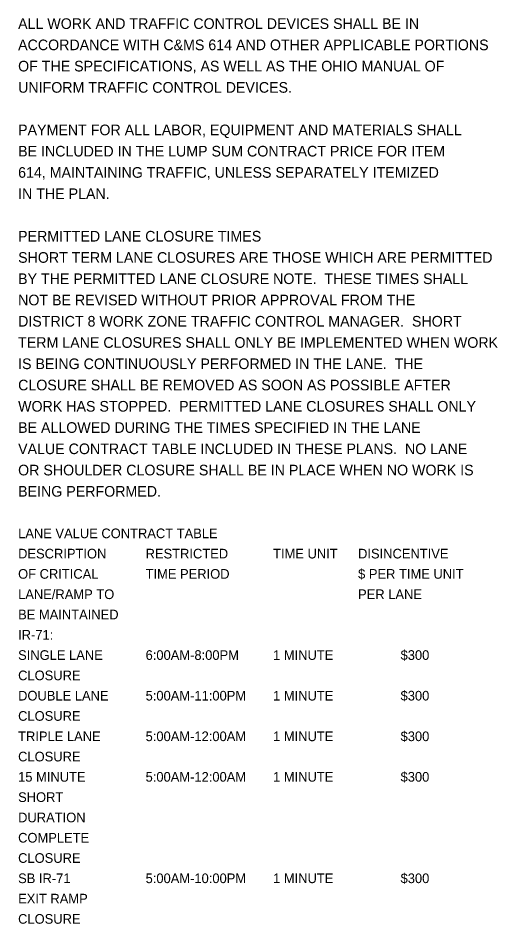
# Model space of a CAD drawing. Extents: x -98 to 46, y -2 to 66.
# Drawn here: x -97.61 to -91.28, y 54.03 to 65.96 of the extents above; entities that cross this region are included whole.
import ezdxf

# ---------------------------------------------------------------- set-up
doc = ezdxf.new("R2010")
doc.units = 0
doc.layers.add('Default', color=7, linetype='Continuous')

msp = doc.modelspace()

# ---------------------------------------------------------------- texts
at = {"layer": 'Default'}
for s, height, p in [('ALL WORK AND TRAFFIC CONTROL DEVICES SHALL BE IN ', 0.14, (-97.607, 65.818)), ('ACCORDANCE WITH C&MS 614 AND OTHER APPLICABLE PORTIONS ', 0.14, (-97.607, 65.538)), ('OF THE SPECIFICATIONS, AS WELL AS THE OHIO MANUAL OF ', 0.14, (-97.607, 65.258)), ('UNIFORM TRAFFIC CONTROL DEVICES.', 0.14, (-97.607, 64.978)), ('PAYMENT FOR ALL LABOR, EQUIPMENT AND MATERIALS SHALL ', 0.14, (-97.607, 64.418)), ('BE INCLUDED IN THE LUMP SUM CONTRACT PRICE FOR ITEM ', 0.14, (-97.607, 64.138)), ('614, MAINTAINING TRAFFIC, UNLESS SEPARATELY ITEMIZED ', 0.14, (-97.607, 63.858)), ('IN THE PLAN.', 0.14, (-97.607, 63.578)), ('PERMITTED LANE CLOSURE TIMES', 0.14, (-97.607, 63.018)), ('SHORT TERM LANE CLOSURES ARE THOSE WHICH ARE PERMITTED ', 0.14, (-97.607, 62.738)), ('BY THE PERMITTED LANE CLOSURE NOTE.  THESE TIMES SHALL ', 0.14, (-97.607, 62.458)), ('NOT BE REVISED WITHOUT PRIOR APPROVAL FROM THE ', 0.14, (-97.607, 62.178)), ('DISTRICT 8 WORK ZONE TRAFFIC CONTROL MANAGER.  SHORT ', 0.14, (-97.607, 61.898)), ('TERM LANE CLOSURES SHALL ONLY BE IMPLEMENTED WHEN WORK ', 0.14, (-97.607, 61.618)), ('IS BEING CONTINUOUSLY PERFORMED IN THE LANE.  THE ', 0.14, (-97.607, 61.338)), ('CLOSURE SHALL BE REMOVED AS SOON AS POSSIBLE AFTER ', 0.14, (-97.607, 61.058)), ('WORK HAS STOPPED.  PERMITTED LANE CLOSURES SHALL ONLY ', 0.14, (-97.607, 60.778)), ('BE ALLOWED DURING THE TIMES SPECIFIED IN THE LANE ', 0.14, (-97.607, 60.498)), ('VALUE CONTRACT TABLE INCLUDED IN THESE PLANS.  NO LANE ', 0.14, (-97.607, 60.218)), ('OR SHOULDER CLOSURE SHALL BE IN PLACE WHEN NO WORK IS ', 0.14, (-97.607, 59.938)), ('BEING PERFORMED.', 0.14, (-97.607, 59.658)), ('LANE VALUE CONTRACT TABLE', 0.12727, (-97.607, 59.111)), ('DESCRIPTION', 0.12727, (-97.607, 58.844)), ('RESTRICTED', 0.1273, (-95.927, 58.844)), ('TIME UNIT', 0.1273, (-94.247, 58.844)), ('DISINCENTIVE', 0.12727, (-93.127, 58.844)), ('OF CRITICAL ', 0.12727, (-97.607, 58.577)), ('TIME PERIOD', 0.12727, (-95.927, 58.577)), ('$ PER TIME UNIT', 0.12727, (-93.127, 58.577)), ('LANE/RAMP TO', 0.12727, (-97.607, 58.309)), ('PER LANE', 0.1273, (-93.127, 58.309)), ('BE MAINTAINED', 0.12727, (-97.607, 58.042)), ('IR-71:', 0.1273, (-97.607, 57.775)), ('SINGLE LANE', 0.12727, (-97.607, 57.508)), ('6:00AM-8:00PM', 0.12727, (-95.927, 57.508)), ('1 MINUTE', 0.1273, (-94.247, 57.508)), ('$300', 0.1273, (-92.567, 57.508)), ('CLOSURE ', 0.1273, (-97.607, 57.24)), ('DOUBLE LANE', 0.12727, (-97.607, 56.973)), ('5:00AM-11:00PM', 0.12727, (-95.927, 56.973)), ('1 MINUTE', 0.1273, (-94.247, 56.973)), ('$300', 0.1273, (-92.567, 56.973)), ('CLOSURE', 0.1273, (-97.607, 56.706)), ('TRIPLE LANE', 0.12727, (-97.607, 56.438)), ('5:00AM-12:00AM', 0.12727, (-95.927, 56.438)), ('1 MINUTE', 0.1273, (-94.247, 56.438)), ('$300', 0.1273, (-92.567, 56.438)), ('CLOSURE', 0.1273, (-97.607, 56.171)), ('15 MINUTE', 0.1273, (-97.607, 55.904)), ('5:00AM-12:00AM', 0.12727, (-95.927, 55.904)), ('1 MINUTE', 0.1273, (-94.247, 55.904)), ('$300', 0.1273, (-92.567, 55.904)), ('SHORT', 0.1273, (-97.607, 55.637)), ('DURATION', 0.1273, (-97.607, 55.369)), ('COMPLETE', 0.1273, (-97.607, 55.102)), ('CLOSURE', 0.1273, (-97.607, 54.835)), ('SB IR-71', 0.1273, (-97.607, 54.568)), ('5:00AM-10:00PM', 0.12727, (-95.927, 54.568)), ('1 MINUTE', 0.1273, (-94.247, 54.568)), ('$300', 0.1273, (-92.567, 54.568)), ('EXIT RAMP', 0.1273, (-97.607, 54.3)), ('CLOSURE', 0.1273, (-97.607, 54.033))]:
    msp.add_text(s, height=height, dxfattribs=at).set_placement(p)

doc.saveas('drawing.dxf')
